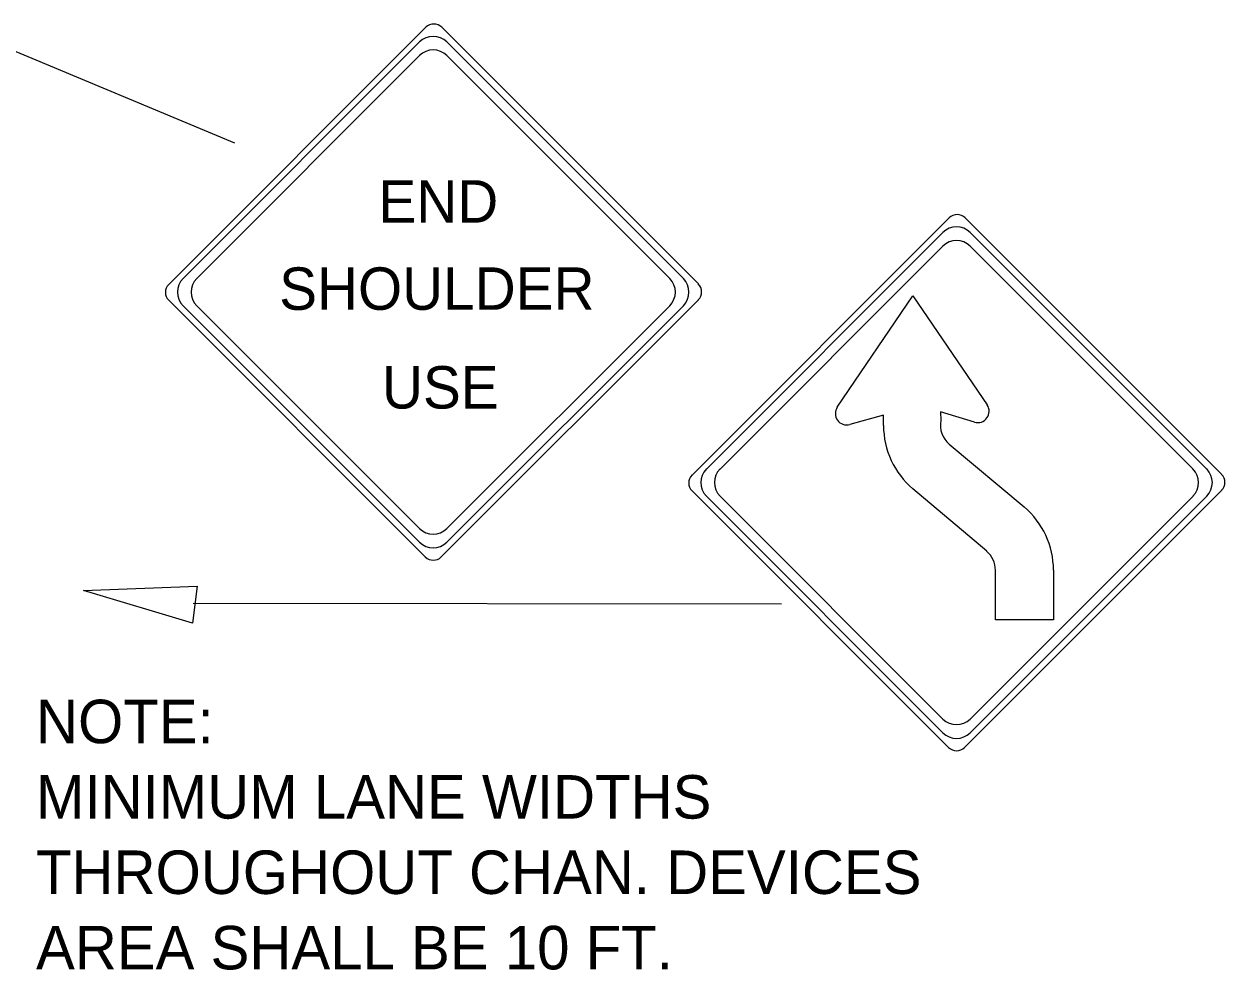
# Model space of a CAD drawing. Extents: x 1531.38 to 1538.58, y 1529.59 to 1539.28.
# Drawn here: x 1536.84 to 1538.496, y 1535.106 to 1536.411 of the extents above; entities that cross this region are included whole.
import ezdxf

# ---------------------------------------------------------------- set-up
doc = ezdxf.new("R2010")
doc.units = 0
for name, color, linetype in [('DETL-DIMS', 7, 'Continuous'), ('DETL-LINE', 7, 'Continuous'), ('DETL-NOTE', 7, 'Continuous')]:
    doc.layers.add(name, color=color, linetype=linetype)

msp = doc.modelspace()

# ---------------------------------------------------------------- linework, layer by layer
at = {"layer": 'DETL-DIMS'}
for p, q in [((1536.8087, 1536.3815), (1537.1301, 1536.2471)), ((1537.0731, 1535.612), (1537.8849, 1535.6112))]:
    msp.add_line(p, q, dxfattribs=at)
msp.add_lwpolyline([(1537.0788, 1535.6355), (1537.0721, 1535.5843), (1536.9217, 1535.6298)], close=True, dxfattribs=at)
at = {"layer": 'DETL-LINE'}
for p, q in [((1537.3941, 1536.4066), (1537.0394, 1536.0519)), ((1537.77, 1536.0526), (1537.4161, 1536.4066)), ((1537.0593, 1536.0601), (1537.3855, 1536.3863)), ((1537.4232, 1536.3863), (1537.7493, 1536.0601)), ((1537.3855, 1536.3675), (1537.0782, 1536.0601)), ((1537.7305, 1536.0601), (1537.4231, 1536.3675)), ((1538.116, 1536.1437), (1537.7613, 1535.7889)), ((1538.4919, 1535.7897), (1538.1379, 1536.1437)), ((1537.7812, 1535.7972), (1538.1074, 1536.1234)), ((1538.145, 1536.1234), (1538.4712, 1535.7972)), ((1538.1074, 1536.1046), (1537.8, 1535.7972)), ((1538.4524, 1535.7972), (1538.145, 1536.1046)), ((1537.7305, 1536.0601), (1537.7305, 1536.0601)), ((1537.0394, 1536.0299), (1537.3933, 1535.676)), ((1537.4153, 1535.676), (1537.77, 1536.0307)), ((1537.9616, 1535.8825), (1538.0658, 1536.0359)), ((1538.0658, 1536.0359), (1538.1684, 1535.8858)), ((1537.3855, 1535.6963), (1537.0593, 1536.0225)), ((1537.0782, 1536.0225), (1537.3855, 1535.7151)), ((1537.7493, 1536.0225), (1537.4232, 1535.6963)), ((1537.4232, 1535.7151), (1537.7305, 1536.0225)), ((1538.104, 1535.876), (1538.1044, 1535.8641)), ((1538.1509, 1535.8618), (1538.104, 1535.876)), ((1538.0254, 1535.8715), (1537.9789, 1535.8585)), ((1538.0254, 1535.8572), (1538.0254, 1535.8715)), ((1538.116, 1535.8315), (1538.2194, 1535.7449)), ((1538.4524, 1535.7972), (1538.4524, 1535.7972)), ((1537.7613, 1535.767), (1538.1152, 1535.4131)), ((1538.1074, 1535.4334), (1537.7812, 1535.7596)), ((1537.8, 1535.7596), (1538.1074, 1535.4522)), ((1538.1678, 1535.6837), (1538.0659, 1535.7699)), ((1538.1372, 1535.4131), (1538.4919, 1535.7678)), ((1538.4712, 1535.7596), (1538.145, 1535.4334)), ((1538.145, 1535.4522), (1538.4524, 1535.7596)), ((1538.18, 1535.589), (1538.1799, 1535.6576)), ((1538.26, 1535.6577), (1538.2601, 1535.5892)), ((1538.2601, 1535.5892), (1538.18, 1535.589))]:
    msp.add_line(p, q, dxfattribs=at)
for centre, radius, start, end in [((1537.4051, 1536.3956), 0.0155, 45, 135), ((1537.4043, 1536.3675), 0.0266, 45, 135), ((1537.4043, 1536.3487), 0.0266, 45, 135), ((1538.127, 1536.1327), 0.0155, 45, 135), ((1538.1262, 1536.1046), 0.0266, 45, 135), ((1538.1262, 1536.0858), 0.0266, 45, 135), ((1537.0781, 1536.0413), 0.0266, 135, 225), ((1537.0969, 1536.0413), 0.0266, 135, 225), ((1537.7117, 1536.0413), 0.0266, 315, 45), ((1537.7305, 1536.0413), 0.0266, 315, 45), ((1537.0504, 1536.0409), 0.0155, 135, 225), ((1537.759, 1536.0416), 0.0155, 315, 45), ((1537.9747, 1535.8737), 0.0157, 145.8336, 285.5836), ((1538.1554, 1535.8769), 0.0157, 253.1964, 34.3543), ((1538.1382, 1535.8577), 0.0343, 169.3489, 229.7591), ((1538.1398, 1535.8573), 0.1144, 180.094, 229.7591), ((1537.8, 1535.7784), 0.0266, 135, 225), ((1537.8188, 1535.7785), 0.0266, 135, 225), ((1538.4335, 1535.7784), 0.0266, 315, 45), ((1538.4524, 1535.7784), 0.0266, 315, 45), ((1537.7723, 1535.778), 0.0155, 135, 225), ((1538.4809, 1535.7788), 0.0155, 315, 45), ((1538.1455, 1535.6575), 0.1144, 0.094, 49.7591), ((1537.4043, 1535.734), 0.0266, 225, 315), ((1537.4043, 1535.7151), 0.0266, 225, 315), ((1537.4043, 1535.6869), 0.0155, 225, 315), ((1538.1455, 1535.6575), 0.0343, 0.094, 49.7591), ((1538.1262, 1535.4711), 0.0266, 225, 315), ((1538.1262, 1535.4522), 0.0266, 225, 315), ((1538.1262, 1535.424), 0.0155, 225, 315)]:
    msp.add_arc(centre, radius, start, end, dxfattribs=at)

# ---------------------------------------------------------------- texts
for s, p in [('END', (1537.3287, 1536.1371)), ('SHOULDER', (1537.1918, 1536.0168)), ('USE', (1537.3336, 1535.8806))]:
    msp.add_text(s, height=0.05854, dxfattribs=at).set_placement(p)
at = {"layer": 'DETL-NOTE'}
for s, p in [('NOTE:', (1536.8564, 1535.4189)), ('MINIMUM LANE WIDTHS', (1536.8564, 1535.3149)), ('THROUGHOUT CHAN. DEVICES', (1536.8564, 1535.2109)), ('AREA SHALL BE 10 FT.', (1536.8564, 1535.1069))]:
    msp.add_text(s, height=0.06, dxfattribs=at).set_placement(p)

doc.saveas('drawing.dxf')
